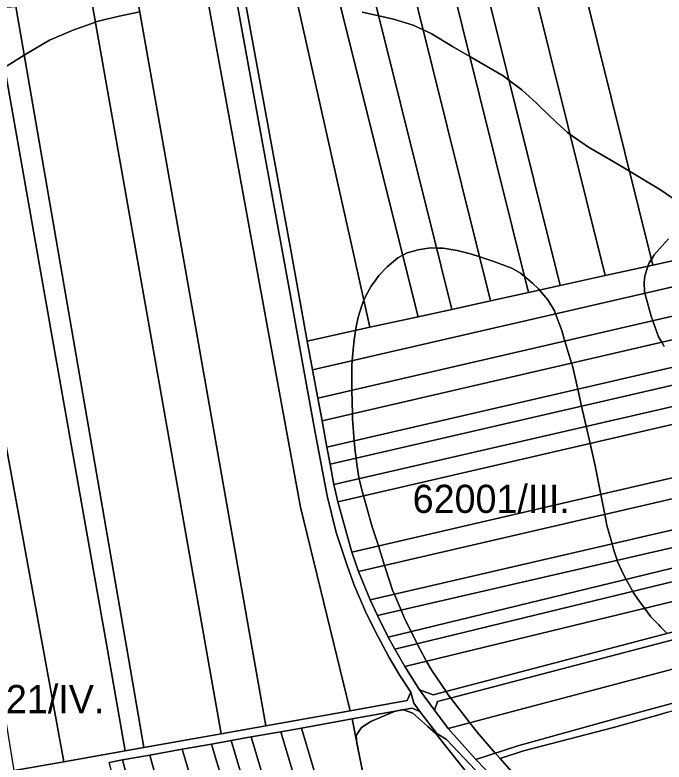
# Model space of a CAD drawing. Extents: x -521939 to -516426, y -1197857 to -1189551.
# Drawn here: x -519681.9 to -519336.3, y -1193402.1 to -1193004.4 of the extents above; entities that cross this region are included whole.
import ezdxf

# ---------------------------------------------------------------- set-up
doc = ezdxf.new("R2010")
doc.units = 0
for name, color, linetype in [('95560013', 7, 'Continuous'), ('95620013', 7, 'Continuous'), ('95640013', 7, 'Continuous'), ('95660013', 7, 'Continuous')]:
    doc.layers.add(name, color=color, linetype=linetype)

msp = doc.modelspace()

# ---------------------------------------------------------------- linework, layer by layer
at = {"layer": '95560013'}
for points in [[(-519568.87, -1192944.42), (-519567.2, -1192943.06), (-519555.74, -1192947.57), (-519549.76, -1192947.78), (-519542.07, -1192950.61), (-519502.89, -1193125.92), (-519492.9, -1193170.62), (-519526.25, -1193178), (-519534.72, -1193131.58)], [(-519467.25, -1193165.07), (-519492.9, -1193170.62), (-519502.89, -1193125.92), (-519542.07, -1192950.61), (-519518.93, -1192958.37), (-519470.42, -1193152.39)], [(-519449.34, -1193161.11), (-519467.25, -1193165.07), (-519470.42, -1193152.39), (-519518.93, -1192958.37), (-519498.2, -1192964.55), (-519455.01, -1193138.3)], [(-519498.2, -1192964.55), (-519474.87, -1192970.68), (-519428.65, -1193156.57), (-519449.34, -1193161.11), (-519455.01, -1193138.3)], [(-519428.65, -1193156.57), (-519474.87, -1192970.68), (-519452.37, -1192975.76), (-519408.54, -1193152.16)], [(-519452.37, -1192975.76), (-519433.72, -1192979.51), (-519391.66, -1193148.43), (-519408.54, -1193152.16)], [(-519391.66, -1193148.43), (-519433.72, -1192979.51), (-519407.22, -1192983.93), (-519367.63, -1193143.15)], [(-519407.22, -1192983.93), (-519379.4, -1192988.21), (-519342.22, -1193137.6), (-519367.63, -1193143.15)], [(-519342.22, -1193137.6), (-519379.4, -1192988.21), (-519316.79, -1192997.86), (-519285.18, -1193125.04)], [(-519616.64, -1192995.84), (-519579.74, -1192993.48), (-519548.08, -1193166.93), (-519529.92, -1193266.42), (-519503.38, -1193374.77), (-519548.25, -1193382.78), (-519553.92, -1193350.7), (-519585.28, -1193173.27)], [(-519681.4, -1192999.94), (-519640.92, -1192997.38), (-519609.36, -1193176.09), (-519577.77, -1193354.97), (-519572.11, -1193387.02), (-519613.26, -1193394.37), (-519620.4, -1193353.04), (-519650.9, -1193176.49)], [(-519640.92, -1192997.38), (-519616.64, -1192995.84), (-519585.28, -1193173.27), (-519553.92, -1193350.7), (-519548.25, -1193382.78), (-519572.11, -1193387.02), (-519577.77, -1193354.97), (-519609.36, -1193176.09)], [(-519728.13, -1193002.94), (-519693.03, -1193000.71), (-519661.73, -1193177.89), (-519632.67, -1193342.39), (-519623.18, -1193396.11), (-519655.8, -1193401.93), (-519668.98, -1193330.14), (-519701.27, -1193154.26), (-519715.07, -1193073.69)], [(-519693.03, -1193000.71), (-519681.4, -1192999.94), (-519650.9, -1193176.49), (-519620.4, -1193353.04), (-519613.26, -1193394.37), (-519623.18, -1193396.11), (-519632.67, -1193342.39), (-519661.73, -1193177.89)], [(-519239.97, -1193115.13), (-519214.83, -1193109.59), (-519172.33, -1193100.26), (-519126.47, -1193090.19), (-519123.99, -1193101.18), (-519170.84, -1193111.98), (-519345.53, -1193152.25), (-519523.43, -1193193.26), (-519526.25, -1193178), (-519492.9, -1193170.62), (-519467.25, -1193165.07), (-519449.34, -1193161.11), (-519428.65, -1193156.57), (-519408.54, -1193152.16), (-519391.66, -1193148.43), (-519367.63, -1193143.15), (-519342.22, -1193137.6), (-519285.18, -1193125.04), (-519272.23, -1193122.17)], [(-519123.99, -1193101.18), (-519120.24, -1193115.95), (-519170.81, -1193127.61), (-519345.68, -1193167.93), (-519520.68, -1193208.28), (-519523.43, -1193193.26), (-519345.53, -1193152.25), (-519170.84, -1193111.98)], [(-519120.24, -1193115.95), (-519116.96, -1193127.76), (-519164.22, -1193138.66), (-519341.25, -1193179.49), (-519518.41, -1193220.35), (-519520.68, -1193208.28), (-519345.68, -1193167.93), (-519170.81, -1193127.61)], [(-519518.41, -1193220.35), (-519341.25, -1193179.49), (-519164.22, -1193138.66), (-519116.96, -1193127.76), (-519112.38, -1193141.37), (-519168.8, -1193154.38), (-519342.31, -1193194.39), (-519515.82, -1193234.4)], [(-519515.82, -1193234.4), (-519342.31, -1193194.39), (-519168.8, -1193154.38), (-519112.38, -1193141.37), (-519109.38, -1193150.03), (-519158.4, -1193161.36), (-519330.9, -1193201.23), (-519514.13, -1193243.58)], [(-519514.13, -1193243.58), (-519330.9, -1193201.23), (-519158.4, -1193161.36), (-519109.38, -1193150.03), (-519105.74, -1193160.59), (-519151.16, -1193171.07), (-519331.67, -1193212.72), (-519512.05, -1193254.34)], [(-519655.8, -1193401.93), (-519682.31, -1193406.66), (-519694.28, -1193333.23), (-519723.2, -1193155.82), (-519701.27, -1193154.26), (-519668.98, -1193330.14)], [(-519512.05, -1193254.34), (-519331.67, -1193212.72), (-519151.16, -1193171.07), (-519105.74, -1193160.59), (-519102.67, -1193169.53), (-519158.33, -1193182.37), (-519334.24, -1193222.95), (-519510.02, -1193263.5)], [(-519102.67, -1193169.53), (-519097.75, -1193196.73), (-519152.16, -1193209.3), (-519327.38, -1193249.78), (-519502.6, -1193290.26), (-519510.02, -1193263.5), (-519334.24, -1193222.95), (-519158.33, -1193182.37)], [(-519502.6, -1193290.26), (-519327.38, -1193249.78), (-519152.16, -1193209.3), (-519097.75, -1193196.73), (-519096.25, -1193207.51), (-519145.49, -1193218.89), (-519324.45, -1193260.25), (-519498.91, -1193300.57)], [(-519498.91, -1193300.57), (-519324.45, -1193260.25), (-519145.49, -1193218.89), (-519096.25, -1193207.51), (-519095.03, -1193223.76), (-519135.65, -1193233.16), (-519314.81, -1193274.62), (-519492.76, -1193315.8)], [(-519492.76, -1193315.8), (-519314.81, -1193274.62), (-519135.65, -1193233.16), (-519095.03, -1193223.76), (-519094.71, -1193233.1), (-519131.02, -1193241.48), (-519310.1, -1193282.81), (-519488.92, -1193324.08)], [(-519094.71, -1193233.1), (-519094.15, -1193241.05), (-519147.76, -1193254.09), (-519314.51, -1193294.65), (-519483.11, -1193335.66), (-519488.92, -1193324.08), (-519310.1, -1193282.81), (-519131.02, -1193241.48)], [(-519094.15, -1193241.05), (-519094.48, -1193248.3), (-519130.26, -1193257.01), (-519304.97, -1193299.54), (-519479.68, -1193342.07), (-519483.11, -1193335.66), (-519314.51, -1193294.65), (-519147.76, -1193254.09)], [(-519479.68, -1193342.07), (-519304.97, -1193299.54), (-519130.26, -1193257.01), (-519094.48, -1193248.3), (-519096.2, -1193259.2), (-519126.3, -1193266.53), (-519300.33, -1193308.91), (-519474.36, -1193351.29)], [(-519096.2, -1193259.2), (-519096.57, -1193261.51), (-519110.89, -1193271.43), (-519142.38, -1193283.13), (-519283.48, -1193320.18), (-519459.16, -1193366.31), (-519466.55, -1193363.58), (-519474.36, -1193351.29), (-519300.33, -1193308.91), (-519126.3, -1193266.53)], [(-519458.56, -1193374.41), (-519456.94, -1193369.86), (-519284.36, -1193324.57), (-519240.31, -1193313.01), (-519245.94, -1193321.3), (-519245.64, -1193323.44), (-519244.89, -1193329.7), (-519279.58, -1193338.87), (-519451.29, -1193384.26)], [(-519244.89, -1193329.7), (-519242.56, -1193344.82), (-519272.27, -1193354.6), (-519363, -1193379.33), (-519414.21, -1193393.4), (-519436.58, -1193400.77), (-519451.29, -1193384.26), (-519279.58, -1193338.87)], [(-519502.33, -1193379.15), (-519480.86, -1193488.16), (-519453.95, -1193570.4), (-519447.84, -1193614.85), (-519389.47, -1193750.04), (-519384.42, -1193774.3), (-519408.2, -1193790.66), (-519424.96, -1193734.42), (-519477.18, -1193559.19), (-519529.4, -1193383.96)], [(-519529.4, -1193383.96), (-519477.18, -1193559.19), (-519424.96, -1193734.42), (-519408.2, -1193790.66), (-519418.05, -1193797.11), (-519436.86, -1193733.88), (-519488.2, -1193561.3), (-519540.37, -1193385.93)], [(-519556.16, -1193388.74), (-519504.45, -1193562.19), (-519453.22, -1193734.03), (-519431.74, -1193806.08), (-519441.36, -1193812.44), (-519460.82, -1193746.98), (-519513.84, -1193568.63), (-519566.75, -1193390.65)], [(-519540.37, -1193385.93), (-519488.2, -1193561.3), (-519436.86, -1193733.88), (-519418.05, -1193797.11), (-519431.74, -1193806.08), (-519453.22, -1193734.03), (-519504.45, -1193562.19), (-519556.16, -1193388.74)], [(-519577.25, -1193392.51), (-519525.65, -1193566.15), (-519473.42, -1193741.91), (-519450.66, -1193818.5), (-519464.32, -1193827.57), (-519490.71, -1193738.79), (-519541.76, -1193567.05), (-519592.81, -1193395.31)], [(-519441.36, -1193812.44), (-519450.66, -1193818.5), (-519473.42, -1193741.91), (-519525.65, -1193566.15), (-519577.25, -1193392.51), (-519566.75, -1193390.65), (-519513.84, -1193568.63), (-519460.82, -1193746.98)], [(-519464.32, -1193827.57), (-519486.62, -1193842.93), (-519514.5, -1193742.52), (-519562.28, -1193570.44), (-519610.06, -1193398.36), (-519592.81, -1193395.31), (-519541.76, -1193567.05), (-519490.71, -1193738.79)], [(-519610.06, -1193398.36), (-519562.28, -1193570.44), (-519514.5, -1193742.52), (-519486.62, -1193842.93), (-519503.63, -1193854.82), (-519531.55, -1193750.06), (-519578.07, -1193575.51), (-519624.59, -1193400.96)], [(-519631.73, -1193402.24), (-519624.59, -1193400.96), (-519578.07, -1193575.51), (-519531.55, -1193750.06), (-519503.63, -1193854.82), (-519509.92, -1193859.26), (-519540.03, -1193746.29), (-519585.9, -1193574.19)]]:
    msp.add_lwpolyline(points, close=True, dxfattribs=at)
at = {"layer": '95620013'}
msp.add_lwpolyline([(-519049.8, -1193274.26), (-519040.03, -1193304.65), (-519061.29, -1193334.23), (-519127.73, -1193353.98), (-519195.16, -1193370.61), (-519207.67, -1193377.01), (-519216.77, -1193386.17), (-519224.13, -1193393.57), (-519244.63, -1193400.06), (-519323.14, -1193420.3), (-519400.65, -1193437.87), (-519436.58, -1193400.77), (-519414.21, -1193393.4), (-519363, -1193379.33), (-519272.27, -1193354.6), (-519242.56, -1193344.82), (-519244.89, -1193329.7), (-519245.64, -1193323.44), (-519072.06, -1193279.85)], close=True, dxfattribs=at)
msp.add_lwpolyline([(-519480.86, -1193488.16), (-519502.33, -1193379.15), (-519470.46, -1193373.47), (-519466.38, -1193375.11), (-519457.37, -1193386.9), (-519452.18, -1193390.07), (-519405.79, -1193439.04)], dxfattribs=at)
at = {"layer": '95640013'}
for points in [[(-519568.87, -1192944.42), (-519534.72, -1193131.58), (-519526.25, -1193178), (-519523.43, -1193193.26), (-519520.68, -1193208.28), (-519518.41, -1193220.35), (-519515.82, -1193234.4), (-519514.13, -1193243.58), (-519512.05, -1193254.34), (-519510.02, -1193263.5), (-519502.6, -1193290.26), (-519498.91, -1193300.57), (-519492.76, -1193315.8), (-519488.92, -1193324.08), (-519483.11, -1193335.66), (-519479.68, -1193342.07), (-519474.36, -1193351.29), (-519466.55, -1193363.58), (-519458.56, -1193374.41), (-519451.29, -1193384.26), (-519436.58, -1193400.77), (-519400.65, -1193437.87)], [(-519567.38, -1192977.66), (-519550.99, -1193067.69), (-519542.14, -1193116.18), (-519535.25, -1193153.85), (-519528.39, -1193191.55), (-519522, -1193226.57), (-519515.74, -1193260.34), (-519510.86, -1193279.84), (-519505.08, -1193297.39), (-519501.24, -1193308), (-519495.18, -1193322.01), (-519490.34, -1193332.09), (-519482.58, -1193346.45), (-519476.92, -1193356.09), (-519471.11, -1193364.85), (-519473, -1193369.35), (-519503.38, -1193374.77), (-519529.92, -1193266.42), (-519548.08, -1193166.93), (-519579.74, -1192993.48)], [(-519405.79, -1193439.04), (-519452.18, -1193390.07), (-519457.37, -1193386.9), (-519466.38, -1193375.11), (-519469.48, -1193370.72), (-519471.11, -1193364.85), (-519476.92, -1193356.09), (-519482.58, -1193346.45), (-519490.34, -1193332.09), (-519495.18, -1193322.01), (-519501.24, -1193308), (-519505.08, -1193297.39), (-519510.86, -1193279.84), (-519515.74, -1193260.34), (-519522, -1193226.57), (-519528.39, -1193191.55), (-519535.25, -1193153.85), (-519542.14, -1193116.18), (-519550.99, -1193067.69), (-519567.38, -1192977.66)], [(-519682.31, -1193406.66), (-519655.8, -1193401.93), (-519623.18, -1193396.11), (-519613.26, -1193394.37), (-519572.11, -1193387.02), (-519548.25, -1193382.78), (-519503.38, -1193374.77), (-519473, -1193369.35), (-519471.11, -1193364.85), (-519469.48, -1193370.72), (-519466.38, -1193375.11), (-519470.46, -1193373.47), (-519502.33, -1193379.15), (-519529.4, -1193383.96), (-519540.37, -1193385.93), (-519556.16, -1193388.74), (-519566.75, -1193390.65), (-519577.25, -1193392.51), (-519592.81, -1193395.31), (-519610.06, -1193398.36), (-519624.59, -1193400.96), (-519631.73, -1193402.24)]]:
    msp.add_lwpolyline(points, dxfattribs=at)
msp.add_lwpolyline([(-519110.89, -1193271.43), (-519096.57, -1193261.51), (-519083.46, -1193249.19), (-519064.08, -1193221.98), (-519063.8, -1193218.73), (-519061.2, -1193228.34), (-519057.96, -1193237.27), (-519065.42, -1193233.19), (-519067.67, -1193235.07), (-519075.4, -1193246.52), (-519081.5, -1193254.17), (-519089.06, -1193261.77), (-519097.04, -1193268.18), (-519106.02, -1193274.02), (-519115.87, -1193279.15), (-519124.36, -1193282.37), (-519240.31, -1193313.01), (-519284.36, -1193324.57), (-519456.94, -1193369.86), (-519458.56, -1193374.41), (-519466.55, -1193363.58), (-519459.16, -1193366.31), (-519283.48, -1193320.18), (-519142.38, -1193283.13)], close=True, dxfattribs=at)
at = {"layer": '95660013'}
for points in [[(-519615.42, -1193002.74), (-519626.44, -1193005), (-519638.2, -1193007.9), (-519639.01, -1193008.19), (-519651.36, -1193012.6), (-519663.41, -1193017.87), (-519674.35, -1193024.1), (-519676.94, -1193025.74), (-519687.44, -1193032.37)], [(-519687.44, -1193032.37), (-519676.94, -1193025.74), (-519674.35, -1193024.1), (-519663.41, -1193017.87), (-519651.36, -1193012.6), (-519639.01, -1193008.19), (-519638.2, -1193007.9), (-519626.44, -1193005), (-519615.42, -1193002.74)], [(-519331.56, -1193102.02), (-519338.28, -1193097.5), (-519354.68, -1193087.53), (-519356.58, -1193086.38), (-519365.14, -1193081.36), (-519376.53, -1193074.67), (-519386.33, -1193067.93), (-519387.66, -1193067.02), (-519393.69, -1193061.45), (-519402.5, -1193053.11), (-519404.32, -1193051.39), (-519412, -1193044.18), (-519418.9, -1193039.05), (-519421.97, -1193036.76), (-519439.77, -1193026.48), (-519448.86, -1193021.23), (-519460.22, -1193014.28), (-519464.51, -1193012.34), (-519469.96, -1193009.87), (-519480.39, -1193006.63), (-519488.17, -1193004.9), (-519497.08, -1193002.92)], [(-519497.08, -1193002.92), (-519488.17, -1193004.9), (-519480.39, -1193006.63), (-519469.96, -1193009.87), (-519464.51, -1193012.34), (-519460.22, -1193014.28), (-519448.86, -1193021.23), (-519439.77, -1193026.48), (-519421.97, -1193036.76), (-519418.9, -1193039.05), (-519412, -1193044.18), (-519404.32, -1193051.39), (-519402.5, -1193053.11), (-519393.69, -1193061.45), (-519387.66, -1193067.02), (-519386.33, -1193067.93), (-519376.53, -1193074.67), (-519365.14, -1193081.36), (-519356.58, -1193086.38), (-519354.68, -1193087.53), (-519338.28, -1193097.5), (-519331.56, -1193102.02)], [(-519336.31, -1193180.84), (-519337.56, -1193178.64), (-519339.21, -1193175.74), (-519342.37, -1193167.17), (-519343.27, -1193164.73), (-519346.54, -1193152.48), (-519346.74, -1193151.75), (-519346.86, -1193146.76), (-519346.51, -1193143.29), (-519346.06, -1193141.59), (-519345.59, -1193139.81), (-519344.94, -1193138.19), (-519344.91, -1193138.11), (-519344.19, -1193136.33), (-519343.01, -1193134.43), (-519342.81, -1193134.11), (-519341.53, -1193132.04), (-519337.11, -1193127.08), (-519333.99, -1193123.58)], [(-519333.99, -1193123.58), (-519337.11, -1193127.08), (-519341.53, -1193132.04), (-519342.81, -1193134.11), (-519343.01, -1193134.43), (-519344.19, -1193136.33), (-519344.91, -1193138.11), (-519344.94, -1193138.19), (-519345.59, -1193139.81), (-519346.06, -1193141.59), (-519346.51, -1193143.29), (-519346.86, -1193146.76), (-519346.74, -1193151.75), (-519346.54, -1193152.48), (-519343.27, -1193164.73), (-519342.37, -1193167.17), (-519339.21, -1193175.74), (-519337.56, -1193178.64), (-519336.31, -1193180.84)], [(-519334.53, -1193375.59), (-519337.96, -1193376.56), (-519363.33, -1193383.76), (-519411.2, -1193396.08), (-519423.63, -1193400.22), (-519425.42, -1193398.18), (-519425.46, -1193398.13), (-519426.15, -1193397.33), (-519435.82, -1193386.15), (-519439.66, -1193381.19), (-519449.86, -1193368), (-519451.24, -1193366.21), (-519452.38, -1193364.53), (-519459.93, -1193353.4), (-519462.79, -1193348.47), (-519463.12, -1193347.9), (-519467.67, -1193339.15), (-519469.03, -1193336.54), (-519470.9, -1193332.69), (-519474.59, -1193325.12), (-519476.29, -1193321.17), (-519479.89, -1193312.82), (-519480.85, -1193310.58), (-519484.62, -1193298.98), (-519485.12, -1193297.38), (-519488.41, -1193286.98), (-519491.63, -1193276.82), (-519496.35, -1193260.35), (-519497.08, -1193257.81), (-519498.56, -1193251.23), (-519498.94, -1193249.52), (-519500.04, -1193242.22), (-519500.27, -1193240.38), (-519500.73, -1193236.6), (-519501.2, -1193231.03), (-519502.18, -1193219.3), (-519502.24, -1193216.62), (-519502.51, -1193204.09), (-519502.53, -1193203.18), (-519502.53, -1193190.9), (-519502.3, -1193188.39), (-519501.44, -1193178.87), (-519500.54, -1193172.31), (-519500.28, -1193170.41), (-519499.17, -1193165.28), (-519497.08, -1193158.44), (-519496.12, -1193156.23), (-519495.11, -1193153.92), (-519492.21, -1193148.71), (-519489.75, -1193145.32), (-519488.16, -1193143.14), (-519483.75, -1193138.39), (-519477.96, -1193133.64), (-519475.45, -1193132.26), (-519473.09, -1193130.97), (-519467.29, -1193129.35), (-519464.07, -1193128.9), (-519461.75, -1193128.57), (-519460.69, -1193128.42), (-519457.45, -1193128.48), (-519453.96, -1193128.54), (-519446.54, -1193129.81), (-519439.36, -1193131.55), (-519434.47, -1193133.18), (-519427.53, -1193135.49), (-519417.33, -1193139.2), (-519412.7, -1193141.75), (-519410.72, -1193143.38), (-519408.76, -1193145), (-519406.42, -1193147.18), (-519403.19, -1193150.21), (-519402.64, -1193150.86), (-519398.21, -1193156.01), (-519394.73, -1193161.8), (-519394.11, -1193163.45), (-519390.79, -1193172.35), (-519389.11, -1193177.94), (-519385.57, -1193189.71), (-519385.11, -1193191.24), (-519382.28, -1193203.61), (-519380.22, -1193212.63), (-519378.46, -1193220.32), (-519377.77, -1193223.36), (-519375.67, -1193232.51), (-519372.94, -1193244.45), (-519370, -1193259.63), (-519367.94, -1193270.3), (-519367.22, -1193274.01), (-519366.8, -1193276.21), (-519364.75, -1193283.35), (-519363.99, -1193285.98), (-519363.2, -1193288.76), (-519361.32, -1193294.63), (-519361.23, -1193294.9), (-519359.15, -1193299.6), (-519358.1, -1193301.97), (-519356.5, -1193304.86), (-519352.99, -1193311.23), (-519351.96, -1193313.1), (-519349.7, -1193316.15), (-519346.7, -1193320.2), (-519343.38, -1193324.69), (-519339.13, -1193329.04), (-519338.14, -1193330.05), (-519334.65, -1193333.62)], [(-519334.65, -1193333.62), (-519338.14, -1193330.05), (-519339.13, -1193329.04), (-519343.38, -1193324.69), (-519346.7, -1193320.2), (-519349.7, -1193316.15), (-519351.96, -1193313.1), (-519352.99, -1193311.23), (-519356.5, -1193304.86), (-519358.1, -1193301.97), (-519359.15, -1193299.6), (-519361.23, -1193294.9), (-519361.32, -1193294.63), (-519363.2, -1193288.76), (-519363.99, -1193285.98), (-519364.75, -1193283.35), (-519366.8, -1193276.21), (-519367.22, -1193274.01), (-519367.94, -1193270.3), (-519370, -1193259.63), (-519372.94, -1193244.45), (-519375.67, -1193232.51), (-519377.77, -1193223.36), (-519378.46, -1193220.32), (-519380.22, -1193212.63), (-519382.28, -1193203.61), (-519385.11, -1193191.24), (-519385.57, -1193189.71), (-519389.11, -1193177.94), (-519390.79, -1193172.35), (-519394.11, -1193163.45), (-519394.73, -1193161.8), (-519398.21, -1193156.01), (-519402.64, -1193150.86), (-519403.19, -1193150.21), (-519406.42, -1193147.18), (-519408.76, -1193145), (-519410.72, -1193143.38), (-519412.7, -1193141.75), (-519417.33, -1193139.2), (-519427.53, -1193135.49), (-519434.47, -1193133.18), (-519439.36, -1193131.55), (-519446.54, -1193129.81), (-519453.96, -1193128.54), (-519457.45, -1193128.48), (-519460.69, -1193128.42), (-519461.75, -1193128.57), (-519464.07, -1193128.9), (-519467.29, -1193129.35), (-519473.09, -1193130.97), (-519475.45, -1193132.26), (-519477.96, -1193133.64), (-519483.75, -1193138.39), (-519488.16, -1193143.14), (-519489.75, -1193145.32), (-519492.21, -1193148.71), (-519495.11, -1193153.92), (-519496.12, -1193156.23), (-519497.08, -1193158.44), (-519499.17, -1193165.28), (-519500.28, -1193170.41), (-519500.54, -1193172.31), (-519501.44, -1193178.87), (-519502.3, -1193188.39), (-519502.53, -1193190.9), (-519502.53, -1193203.18), (-519502.51, -1193204.09), (-519502.24, -1193216.62), (-519502.18, -1193219.3), (-519501.2, -1193231.03), (-519500.73, -1193236.6), (-519500.27, -1193240.38), (-519500.04, -1193242.22), (-519498.94, -1193249.52), (-519498.56, -1193251.23), (-519497.08, -1193257.81), (-519496.35, -1193260.35), (-519491.63, -1193276.82), (-519488.41, -1193286.98), (-519485.12, -1193297.38), (-519484.62, -1193298.98), (-519480.85, -1193310.58), (-519479.89, -1193312.82), (-519476.29, -1193321.17), (-519474.59, -1193325.12), (-519470.9, -1193332.69), (-519469.03, -1193336.54), (-519467.67, -1193339.15), (-519463.12, -1193347.9), (-519462.79, -1193348.47), (-519459.93, -1193353.4), (-519452.38, -1193364.53), (-519451.24, -1193366.21), (-519449.86, -1193368), (-519439.66, -1193381.19), (-519435.82, -1193386.15), (-519426.15, -1193397.33), (-519425.46, -1193398.13), (-519425.42, -1193398.18), (-519423.63, -1193400.22), (-519394.68, -1193433.31)], [(-519394.68, -1193433.31), (-519423.63, -1193400.22), (-519411.2, -1193396.08), (-519363.33, -1193383.76), (-519337.96, -1193376.56), (-519334.53, -1193375.59), (-519311.43, -1193369.04), (-519297.24, -1193367.04), (-519277.57, -1193361.67), (-519273.69, -1193360.61), (-519233.36, -1193349.16), (-519233.91, -1193347.34), (-519234.47, -1193345.5), (-519241.51, -1193322.4), (-519241.77, -1193321.56), (-519238.87, -1193320.59), (-519238.26, -1193320.39), (-519208.11, -1193310.3), (-519197.48, -1193307.35), (-519185.97, -1193304.16), (-519179.05, -1193302.24), (-519123.5, -1193286.83), (-519106.86, -1193280.88), (-519090.5, -1193275.02)], [(-519496.37, -1193409.42), (-519499.78, -1193392.08), (-519500.27, -1193387.91), (-519497.31, -1193383.61), (-519492.41, -1193380.52), (-519479.44, -1193375.07), (-519479.06, -1193374.91), (-519475.39, -1193374.12), (-519474.96, -1193374.27), (-519470.01, -1193376.04), (-519462.02, -1193383.2), (-519457.67, -1193387.1), (-519453.32, -1193392.59), (-519433.92, -1193417.09)], [(-519433.92, -1193417.09), (-519453.32, -1193392.59), (-519457.67, -1193387.1), (-519462.02, -1193383.2), (-519470.01, -1193376.04), (-519474.96, -1193374.27), (-519475.39, -1193374.12), (-519479.06, -1193374.91), (-519479.44, -1193375.07), (-519492.41, -1193380.52), (-519497.31, -1193383.61), (-519500.27, -1193387.91), (-519499.78, -1193392.08), (-519496.37, -1193409.42)]]:
    msp.add_lwpolyline(points, dxfattribs=at)

# ---------------------------------------------------------------- texts
for s, rotation, p in [('62001/III.', 0, (-519470.15, -1193269.46)), ('62021/IV.', 360, (-519720.13, -1193376.06))]:
    msp.add_text(s, height=15, rotation=rotation, dxfattribs=at).set_placement(p)

doc.saveas('drawing.dxf')
